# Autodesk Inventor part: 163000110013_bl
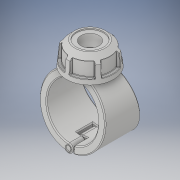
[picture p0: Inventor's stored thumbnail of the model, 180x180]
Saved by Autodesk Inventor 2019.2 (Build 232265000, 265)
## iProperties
Created: 2022-02
Part Number: 163000110013_bl
Material: Generic
Description: Plassadle Threaded 110x1 1/4''
Document SubType Name: Modeling
Designer: comp2
Density: 1 g/cm^3
Appearance: Default
Author: comp2
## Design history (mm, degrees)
derived "16300.ipt"
feature "Solid1::16300.ipt" dims "ScaleForDerivedMember" = 10
feature "Solid2::16300.ipt" dims "ScaleForDerivedMember" = 10
feature "Solid3::16300.ipt" dims "ScaleForDerivedMember" = 10
feature "Solid4::16300.ipt" dims "ScaleForDerivedMember" = 10
tag "TaggingFeature1"
body "Solid1"
body "Solid2"
body "Solid3"
body "Solid4"
other parameters: "d2" = 141 [user parameter], "d3" = 55 [user parameter], "d7" = 133.95 [user parameter], "d8" = 85 deg [user parameter], "d9" = 45 deg [user parameter], "d10" = 102 [user parameter], "d11" = 49 [user parameter], "d12" = 34.7935 [user parameter], "d13" = 42.84 [user parameter], "d14" = 58.428 [user parameter], "d42" = 3.1 [user parameter], "d49" = 2.82 [user parameter], "d50" = 97 [user parameter], "d51" = 0 [user parameter], "d52" = 21.7 [user parameter], "d53" = 77.55 [user parameter], "d54" = 33.95 [user parameter], "d55" = 0 [user parameter], "d56" = 19.4 [user parameter], "d57" = 19.4 [user parameter], "d59" = 0 [user parameter], "d60" = 97 [user parameter], "d61" = 0 [user parameter], "d62" = 33.95 [user parameter], "d63" = 0 [user parameter], "d65" = 0 [user parameter], "d67" = 0 [user parameter], "d69" = 0 [user parameter], "d70" = 1 [user parameter], "d71" = 93.12 [user parameter], "d72" = 0 [user parameter], "d73" = 2 [user parameter], "d78" = 86.7 [user parameter], "d79" = 5.1 [user parameter], "d80" = 60 deg [user parameter], "d81" = 5.1 [user parameter], "d84" = 0 [user parameter], "d85" = 1 [user parameter], "d87" = 360 deg [user parameter], "d122" = 58 [user parameter], "d124" = 42.80128 [user parameter], "d125" = 2.48525 [user parameter], "d129" = 38.952 [user parameter], "d130" = 33.1092 [user parameter], "d131" = 37.7 [user parameter], "d132" = 45 deg [user parameter], "d133" = 26.39 [user parameter], "d134" = 19.476 [user parameter], "d136" = 0 [user parameter], "d138" = 0 [user parameter], "d1" = 25 [user parameter], "B" = 141 [user parameter], "L" = 97 [user parameter], "E_" = 54 [user parameter], "E1" = 102 [user parameter], "H2" = 58 [user parameter], "H3" = 78 [user parameter], "H_costum" = 49 [user parameter], "Rp" = 38.952 [user parameter], "d128" = 49.705 [user parameter]
